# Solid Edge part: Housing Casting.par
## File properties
Title: Housing
Author: Dan
Template: Normal.par
Last saved by: Dan
Revision: 74
Application: Solid Edge
Document Number: P52-001
Material: aluminum
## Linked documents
Piston Housing Core.par
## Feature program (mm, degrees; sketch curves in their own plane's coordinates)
sketch for "unnamed Protrusion 1" plane through (0, 0, 0) normal (1, 0, 0) x-axis (0, 1, 0)
  circle centre (0, 0) radius 47
extrude "unnamed Protrusion 1" add finite 43 along +normal
sketch for "unnamed Protrusion 2" plane through (0, 0, 0) normal (1, 0, 0) x-axis (0, 1, 0)
  line (-53.9527, 38.8498) -> (-50.75, 0)
  line (-50.75, 0) -> (-53.9527, -38.8498)
  arc centre (-40, -40) radius 14 from (-40.4886, -53.9915) to (-53.9527, -38.8498) cw
  line (-40.4886, -53.9915) -> (0, -55.4054)
  line (40.4886, -53.9915) -> (0, -55.4054)
  arc centre (40, -40) radius 14 from (53.9527, -38.8498) to (40.4886, -53.9915) cw
  line (50.75, 0) -> (53.9527, -38.8498)
  line (53.9527, 38.8498) -> (50.75, 0)
  arc centre (40, 40) radius 14 from (40.4886, 53.9915) to (53.9527, 38.8498) cw
  line (40.4886, 53.9915) -> (0, 55.4054)
  line (-40.4886, 53.9915) -> (0, 55.4054)
  arc centre (-40, 40) radius 14 from (-53.9527, 38.8498) to (-40.4886, 53.9915) cw
extrude "unnamed Protrusion 2" add finite 16.41 along -normal
draft "unnamed Draft 1"
fillet "unnamed Round 1"
sketch for "unnamed Protrusion 3" plane through (-13, 0, 0) normal (1, 0, 0) x-axis (0, 1, 0)
extrude "unnamed Protrusion 3" add finite 72 along -normal
sketch for "unnamed RevolvedCutout 1" plane through (0, 0, 0) normal (0, -1, 0) x-axis (1, 0, 0)
  line (-85, 25.5) -> (-82, 25.5)
  line (-82, 25.5) -> (-57.1938, 50.3062)
  arc centre (-51.5369, 44.6494) radius 8 from (-51.8161, 52.6445) to (-57.1938, 50.3062) ccw
  line (-51.8161, 52.6445) -> (-51.8161, 57.098)
revolve "unnamed RevolvedCutout 1" cut full turn 360 deg
fillet "unnamed Round 2"
sketch for "unnamed RevolvedProtrusion 1" plane through (0, 0, 0) normal (0, 0, 1) x-axis (1, 0, 0)
  line (43, 21) -> (43.8787, 21)
  line (43.8787, 21) -> (46, 18.8787)
  line (46, 18.8787) -> (46, 0)
revolve "unnamed RevolvedProtrusion 1" add finite 360 deg about sketch line (46, 0) -> (38.3532, 0)
fillet "unnamed Round 3"
sketch for "unnamed RevolvedProtrusion 2" plane through (0, 0, 0) normal (0, -1, 0) x-axis (1, 0, 0)
revolve "unnamed RevolvedProtrusion 2" add finite 360 deg about sketch line (-85, 0) -> (-86.7128, 0)
sketch for "unnamed RevolvedProtrusion 3" plane through (0, 0, 0) normal (0, 0, 1) x-axis (1, 0, 0)
revolve "unnamed RevolvedProtrusion 3" add full turn 360 deg about sketch line (-152.3351, 0) -> (-60, 0)
sketch for "unnamed RevolvedProtrusion 4" plane through (0, 0, 0) normal (0, -1, 0) x-axis (1, 0, 0)
revolve "unnamed RevolvedProtrusion 4" add finite 360 deg
sketch for "unnamed Protrusion 4" plane through (0, 0, 0) normal (0, 0, 1) x-axis (1, 0, 0)
extrude "unnamed Protrusion 4" add to key point symmetric
sketch for "unnamed Cutout 1" plane through (0, 0, 0) normal (1, 0, 0) x-axis (0, 1, 0)
extrude "unnamed Cutout 1" cut through along +normal
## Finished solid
Body 1: solid body, 17 faces, 16 edges, 1 vertex.
  Faces by surface: torus 6, cylinder 4, plane 4, cone 3
  Edges by curve: circle 16
Body 2: solid body, 145 faces, 323 edges, 180 vertices.
  Faces by surface: blend 60, plane 30, cylinder 25, cone 18, torus 12
  Edges by curve: intersection 122, circle 93, line 78, ellipse 30
Bounding box of the edges (mm; curved faces can reach further): 199.304 x 108.000 x 110.811, from (-151.8043, -54, -55.4054) to (47.5, 54, 55.4054).
Cylindrical faces by radius (mm): R2 x16, R12.6046 x1, R12.8046 x1, R14 x4, R15 x1, R15.2 x1, R25 x1, R25.2 x1, R25.5 x1, R28.0163 x1, R48.5 x1
Conical faces (half-angle, radius in mm at the cone's reference point): 2 deg R10 x4, 2 deg R54 x6, 19.9523 deg R23.7772 x1, 45 deg R21.629 x1, 45 deg R25.5 x1, 88 deg R0 x1, 88 deg R7.7845 x1, 88 deg R12.5 x1, 88 deg R13.5697 x1, 88 deg R15.2 x1, 88 deg R23.0698 x1, 88 deg R23.0768 x1, 88 deg R46.5698 x1
Toroidal faces (ring radius, tube radius in mm): R0.1079 r44.3294 x1, R13.6046 r0.8 x1, R13.6046 r1 x1, R15.0163 r3 x1, R23 r2 x2, R23 r2.2 x2, R24.3 r1.2 x1, R24.7172 r1 x1, R27.5 r2 x1, R44.6494 r8 x6, R46.5 r2 x1
Planar faces by outward normal: +x 3, +z 1, -x 3, -z 1, oblique 26
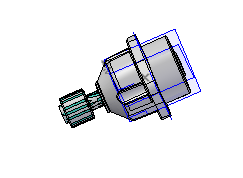
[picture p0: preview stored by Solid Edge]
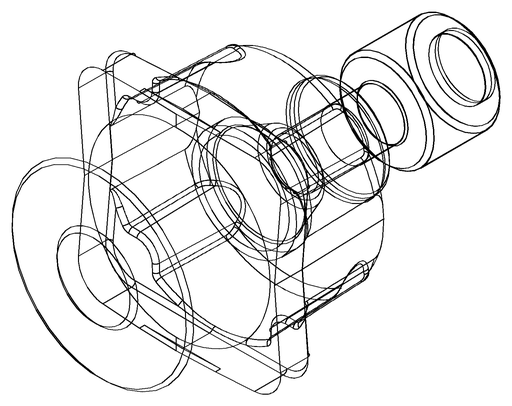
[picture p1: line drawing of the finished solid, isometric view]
